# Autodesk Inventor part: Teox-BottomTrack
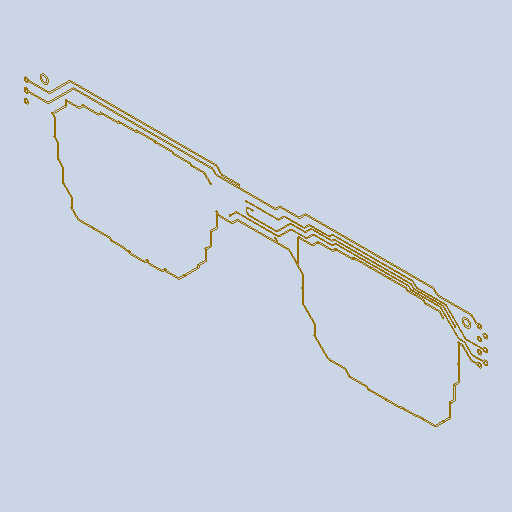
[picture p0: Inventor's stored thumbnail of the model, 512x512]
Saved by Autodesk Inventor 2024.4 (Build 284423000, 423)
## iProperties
Created: 2025-05
Part Number: Teox-BottomTrack
Material: Generic
Document SubType Name: Modeling
Designer: AdminForWorker
Density: 1 g/cm^3
Appearance: Default
Title: Teox-BottomTrack
Author: AdminForWorker
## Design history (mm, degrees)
feature "Composite1"
body "Srf1"
